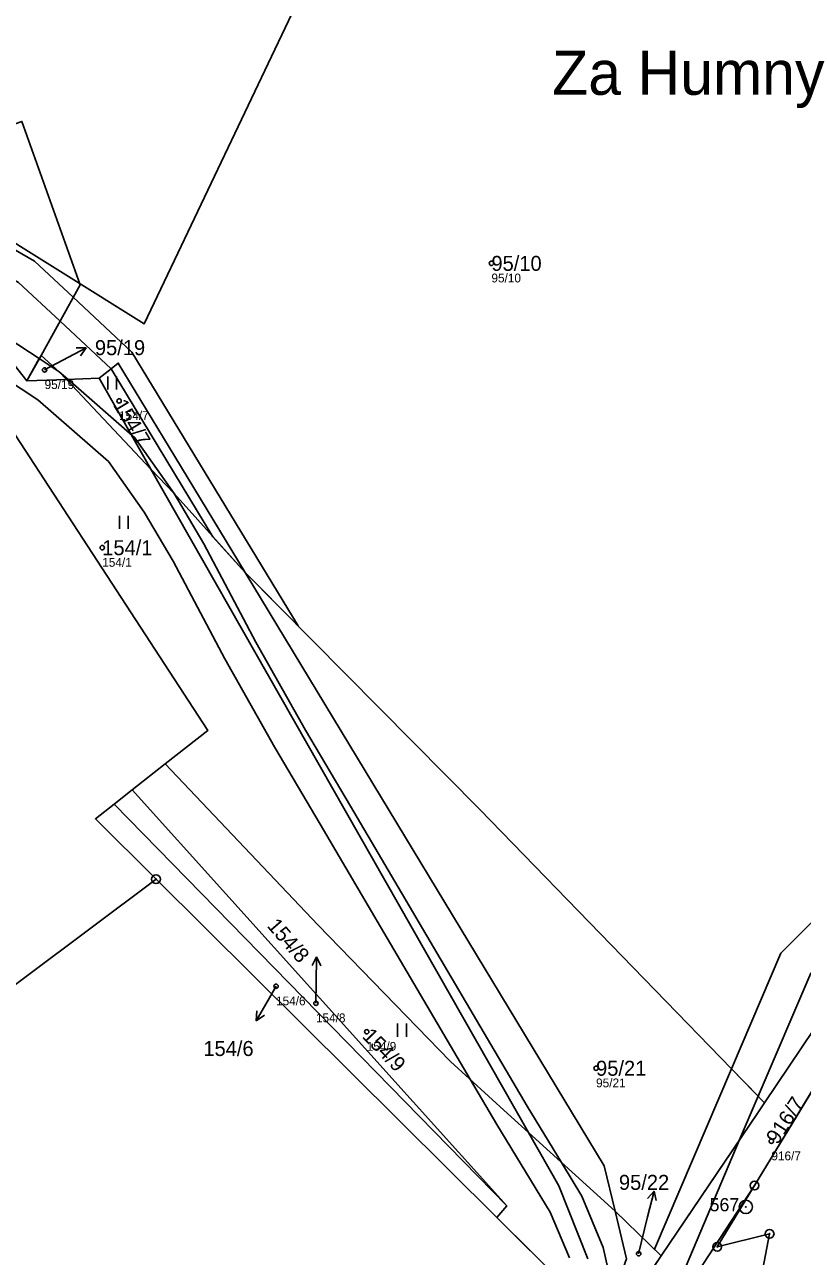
# Model space of a CAD drawing. Extents: x -734504 to -730695, y -1027923 to -1024502.
# Drawn here: x -731981.3 to -731893.3, y -1026758 to -1026618.4 of the extents above; entities that cross this region are included whole.
import ezdxf

# ---------------------------------------------------------------- set-up
doc = ezdxf.new("R2010")
doc.units = 0
for name, color, linetype in [('Definiční body', 7, 'Continuous'), ('Hranice parcel', 7, 'Continuous'), ('Parcelní čísla', 7, 'Continuous'), ('Polygon parcely', 7, 'Continuous'), ('Pop  PČ popisy', 7, 'Continuous'), ('Vnitřní kresba', 7, 'Continuous'), ('Věcná břemena k části', 7, 'Continuous'), ('Značky bodu BP', 7, 'Continuous'), ('Značky kultur', 7, 'Continuous')]:
    doc.layers.add(name, color=color, linetype=linetype)

msp = doc.modelspace()

# ---------------------------------------------------------------- linework, layer by layer
at = {"layer": 'Definiční body'}
for centre in [(-731928.49, -1026645.47), (-731979.09, -1026657.55), (-731970.65, -1026661.06), (-731972.56, -1026677.69), (-731952.88, -1026727.39), (-731948.36, -1026729.31), (-731942.61, -1026732.54), (-731916.64, -1026736.68), (-731896.79, -1026744.95), (-731911.82, -1026757.7)]:
    msp.add_circle(centre, 0.25, dxfattribs=at)
at = {"layer": 'Hranice parcel'}
for p, q in [((-731998.09, -1026637.25), (-731981.09, -1026658.8)), ((-731981.09, -1026658.8), (-731979.49, -1026655.91)), ((-731976.61, -1026658.62), (-731981.09, -1026658.8)), ((-731915.73, -1026747.72), (-731956.39, -1026680.5)), ((-731969.17, -1026705.14), (-731965.42, -1026702.19)), ((-731971.2, -1026706.74), (-731969.17, -1026705.14)), ((-731926.76, -1026752.28), (-731969.17, -1026705.14)), ((-731926.76, -1026752.28), (-731971.2, -1026706.74)), ((-731927.88, -1026753.59), (-731966.47, -1026715.25)), ((-731886.31, -1026729.58), (-731898.7, -1026749.97)), ((-731914.49, -1026752.89), (-731915.73, -1026747.72)), ((-731927.88, -1026753.59), (-731926.76, -1026752.28)), ((-731914.49, -1026752.89), (-731909.26, -1026757.93)), ((-731919.78, -1026761.63), (-731927.88, -1026753.59))]:
    msp.add_line(p, q, dxfattribs=at)
for points in [[(-731979.49, -1026655.91), (-731975.06, -1026647.92), (-731981.65, -1026629.39), (-731996.27, -1026634.52)], [(-731965.42, -1026702.19), (-731960.6, -1026698.4), (-731989.51, -1026654.05), (-731999.43, -1026638.83)], [(-731979.49, -1026655.91), (-731977.42, -1026657.76), (-731976.61, -1026658.62)], [(-731976.61, -1026658.62), (-731972.9, -1026658.47), (-731971.56, -1026657.43), (-731970.74, -1026656.78)], [(-731970.74, -1026656.78), (-731964.35, -1026667.34), (-731956.39, -1026680.5)], [(-731956.39, -1026680.5), (-731964.43, -1026671.55), (-731967.04, -1026668.78), (-731976.61, -1026658.62)], [(-731897.55, -1026740.6), (-731891.98, -1026732.29), (-731883.98, -1026721.82), (-731870.03, -1026706.66), (-731852.36, -1026688.4), (-731836.27, -1026672.06)], [(-731956.39, -1026680.5), (-731929.79, -1026707.37), (-731897.55, -1026740.6)], [(-731965.42, -1026702.19), (-731948.13, -1026720.44), (-731933.11, -1026735.93), (-731926.68, -1026741.8), (-731924.3, -1026743.96), (-731914.49, -1026752.89)], [(-731966.47, -1026715.25), (-731973.34, -1026708.42), (-731971.2, -1026706.74)], [(-732007.28, -1026745.77), (-731989.29, -1026732.31), (-731988.74, -1026731.9), (-731966.47, -1026715.25)], [(-731909.26, -1026757.93), (-731898.31, -1026741.73), (-731897.55, -1026740.6)], [(-731898.7, -1026749.97), (-731907.76, -1026763.82), (-731909.1, -1026766.06)], [(-731898.7, -1026749.97), (-731902.92, -1026756.92), (-731896.99, -1026755.44), (-731899.12, -1026766.53)], [(-731914.49, -1026752.89), (-731913.19, -1026758.29), (-731915.79, -1026765.55)], [(-731917.71, -1026772.7), (-731911.78, -1026761.66), (-731909.26, -1026757.93)]]:
    msp.add_lwpolyline(points, dxfattribs=at)
at = {"layer": 'Polygon parcely'}
for points in [[(-731863.15, -1026642.98), (-731906.94, -1026596.3), (-731941.3, -1026559.94), (-732003.69, -1026606.79), (-732006.1, -1026609.2), (-732012.91, -1026616.02), (-732013.85, -1026616.96), (-732011.19, -1026619.62), (-731996.27, -1026634.52), (-731981.65, -1026629.39), (-731975.06, -1026647.92), (-731979.49, -1026655.91), (-731977.42, -1026657.76), (-731976.61, -1026658.62), (-731972.9, -1026658.47), (-731971.56, -1026657.43), (-731970.74, -1026656.78), (-731964.35, -1026667.34), (-731956.39, -1026680.5), (-731929.79, -1026707.37), (-731897.55, -1026740.6), (-731891.98, -1026732.29)], [(-731907.76, -1026763.82), (-731898.7, -1026749.97), (-731886.31, -1026729.58), (-731884.4, -1026726.44), (-731842.6, -1026684.43), (-731833.2, -1026674.32), (-731829.04, -1026668.66), (-731807.05, -1026644.37), (-731800.24, -1026636.86), (-731792.35, -1026628.32), (-731782.06, -1026616.62), (-731778.03, -1026612.05), (-731780.21, -1026614.31), (-731805.23, -1026640.33), (-731828.58, -1026664.25), (-731836.27, -1026672.06), (-731852.36, -1026688.4), (-731870.03, -1026706.66), (-731883.98, -1026721.82), (-731891.98, -1026732.29), (-731897.55, -1026740.6), (-731898.31, -1026741.73), (-731909.26, -1026757.93), (-731911.78, -1026761.66)], [(-731988.74, -1026731.9), (-731966.47, -1026715.25), (-731973.34, -1026708.42), (-731971.2, -1026706.74), (-731969.17, -1026705.14), (-731965.42, -1026702.19), (-731960.6, -1026698.4), (-731989.51, -1026654.05)]]:
    msp.add_lwpolyline(points, dxfattribs=at)
for points in [[(-731975.06, -1026647.92), (-731981.65, -1026629.39), (-731996.27, -1026634.52), (-731996.97, -1026635.57), (-731998.09, -1026637.25), (-731981.09, -1026658.8), (-731979.49, -1026655.91)], [(-731933.11, -1026735.93), (-731926.68, -1026741.8), (-731924.3, -1026743.96), (-731914.49, -1026752.89), (-731915.73, -1026747.72), (-731956.39, -1026680.5), (-731964.43, -1026671.55), (-731967.04, -1026668.78), (-731976.61, -1026658.62), (-731981.09, -1026658.8), (-731998.09, -1026637.25), (-731998.74, -1026638.02), (-731999.43, -1026638.83), (-731989.51, -1026654.05), (-731960.6, -1026698.4), (-731965.42, -1026702.19), (-731948.13, -1026720.44)], [(-731979.49, -1026655.91), (-731981.09, -1026658.8), (-731976.61, -1026658.62), (-731977.42, -1026657.76)], [(-731970.74, -1026656.78), (-731971.56, -1026657.43), (-731972.9, -1026658.47), (-731976.61, -1026658.62), (-731967.04, -1026668.78), (-731964.43, -1026671.55), (-731956.39, -1026680.5), (-731964.35, -1026667.34)], [(-731909.26, -1026757.93), (-731898.31, -1026741.73), (-731897.55, -1026740.6), (-731929.79, -1026707.37), (-731956.39, -1026680.5), (-731915.73, -1026747.72), (-731914.49, -1026752.89)], [(-731919.78, -1026761.63), (-731915.79, -1026765.55), (-731913.19, -1026758.29), (-731914.49, -1026752.89), (-731924.3, -1026743.96), (-731926.68, -1026741.8), (-731933.11, -1026735.93), (-731948.13, -1026720.44), (-731965.42, -1026702.19), (-731969.17, -1026705.14), (-731926.76, -1026752.28), (-731927.88, -1026753.59)], [(-731926.76, -1026752.28), (-731969.17, -1026705.14), (-731971.2, -1026706.74)], [(-731926.76, -1026752.28), (-731971.2, -1026706.74), (-731973.34, -1026708.42), (-731966.47, -1026715.25), (-731927.88, -1026753.59)], [(-732041.57, -1026826.46), (-732021.92, -1026852.62), (-731966.12, -1026808.48), (-731919.78, -1026761.63), (-731927.88, -1026753.59), (-731966.47, -1026715.25), (-731988.74, -1026731.9), (-731989.29, -1026732.31), (-732007.28, -1026745.77), (-731985.19, -1026775.31), (-731997.89, -1026784.9), (-732020.01, -1026755.28), (-732024.83, -1026758.88), (-732027.73, -1026761.05), (-732068.04, -1026791.19), (-732043.87, -1026823.31)], [(-731896.99, -1026755.44), (-731899.12, -1026766.53), (-731892.84, -1026760.35), (-731891.79, -1026759.14), (-731882.22, -1026753.42), (-731867.68, -1026758.34), (-731883.36, -1026734.14), (-731886.31, -1026729.58), (-731898.7, -1026749.97), (-731902.92, -1026756.92)], [(-731908.97, -1026773), (-731907.29, -1026774.21), (-731903.36, -1026770.7), (-731899.12, -1026766.53), (-731896.99, -1026755.44), (-731902.92, -1026756.92), (-731898.7, -1026749.97), (-731907.76, -1026763.82), (-731909.1, -1026766.06), (-731910.12, -1026767.76)], [(-731913.19, -1026758.29), (-731915.79, -1026765.55), (-731917.71, -1026772.7), (-731911.78, -1026761.66), (-731909.26, -1026757.93), (-731914.49, -1026752.89)]]:
    msp.add_lwpolyline(points, close=True, dxfattribs=at)
at = {"layer": 'Pop  PČ popisy'}
for p, q in [((-731977.03, -1026656.44), (-731974.38, -1026655.03)), ((-731974.38, -1026655.03), (-731975.5, -1026655.06)), ((-731974.38, -1026655.03), (-731975.03, -1026655.94)), ((-731979.09, -1026657.55), (-731977.03, -1026656.44)), ((-731948.28, -1026724.05), (-731948.8, -1026725.04)), ((-731948.33, -1026727.05), (-731948.28, -1026724.05)), ((-731948.28, -1026724.05), (-731947.79, -1026725.06)), ((-731952.88, -1026727.39), (-731953.62, -1026728.69)), ((-731948.36, -1026729.31), (-731948.33, -1026727.05)), ((-731953.62, -1026728.69), (-731955.12, -1026731.29)), ((-731955.12, -1026731.29), (-731955.05, -1026730.17)), ((-731955.12, -1026731.29), (-731954.19, -1026730.67)), ((-731910.8, -1026753.5), (-731910.07, -1026750.59)), ((-731910.07, -1026750.59), (-731910.8, -1026751.44)), ((-731910.07, -1026750.59), (-731909.83, -1026751.68)), ((-731911.82, -1026757.7), (-731910.8, -1026753.5))]:
    msp.add_line(p, q, dxfattribs=at)
at = {"layer": 'Vnitřní kresba'}
for p, q in [((-731972.9, -1026658.47), (-731967.04, -1026668.78)), ((-731967.04, -1026668.78), (-731924.3, -1026743.96)), ((-731924.3, -1026743.96), (-731920.86, -1026750.02)), ((-731917.58, -1026758.29), (-731920.86, -1026750.02))]:
    msp.add_line(p, q, dxfattribs=at)
msp.add_lwpolyline([(-732061.13, -1026537.35), (-732085.01, -1026542.48), (-732078.92, -1026559.32), (-732073.63, -1026577.76), (-732071.73, -1026591.42), (-732069.62, -1026609.74), (-732068.98, -1026636.13), (-732059.46, -1026625.23), (-732039.49, -1026615.52), (-732026.13, -1026613.13), (-732013.67, -1026616.52), (-731996.27, -1026634.52), (-731967.83, -1026652.33), (-731949.59, -1026613.99), (-731927.58, -1026565.74), (-731904.67, -1026526.33)], dxfattribs=at)
at = {"layer": 'Věcná břemena k části'}
for points in [[(-731980.24, -1026645.21), (-731996.97, -1026635.57), (-732001.13, -1026633.18), (-732001.93, -1026633.03), (-731999.49, -1026635.71), (-731998.09, -1026637.25), (-731996.43, -1026639.35), (-731982.04, -1026647.63), (-731977.34, -1026652.03), (-731971.56, -1026657.43), (-731960.03, -1026676.45), (-731956.39, -1026680.5), (-731950.39, -1026686.56), (-731969.2, -1026655.53), (-731975.84, -1026649.32)], [(-731987.78, -1026650.32), (-731981.09, -1026658.8), (-731979.69, -1026656.27), (-731983.11, -1026654.03)], [(-731976.44, -1026658.61), (-731977.42, -1026657.76), (-731976.61, -1026658.62), (-731967.04, -1026668.78), (-731964.43, -1026671.55), (-731968.86, -1026665.24)], [(-731840.03, -1026673.33), (-731837.58, -1026670.8), (-731840.47, -1026668.03), (-731842.89, -1026670.53), (-731895.7, -1026723.64), (-731901.3, -1026736.73), (-731898.28, -1026739.85), (-731892.32, -1026725.92)], [(-731901.3, -1026736.73), (-731910.04, -1026757.17), (-731909.26, -1026757.93), (-731900.42, -1026744.86), (-731898.28, -1026739.85)], [(-732024.55, -1026865.8), (-732022.11, -1026868.92), (-732016.59, -1026864.76), (-732016.09, -1026864.38), (-732015.49, -1026865.31), (-732012.33, -1026862.83), (-732012.87, -1026862), (-732004.32, -1026854.61), (-732002.58, -1026852.67), (-731988.8, -1026840.23), (-731972.85, -1026825.75), (-731946.21, -1026802.13), (-731933.94, -1026790.88), (-731909.79, -1026766.75), (-731907.68, -1026762.03), (-731900.42, -1026744.86), (-731909.26, -1026757.93), (-731911.19, -1026760.79), (-731911.78, -1026761.66), (-731912.67, -1026763.32), (-731917.3, -1026774.14), (-732015.07, -1026858.63), (-732018.93, -1026861.55)]]:
    msp.add_lwpolyline(points, close=True, dxfattribs=at)
for points in [[(-731915.32, -1026759.34), (-731915.82, -1026756.99), (-731918.26, -1026751.17), (-731920.57, -1026747.35), (-731924.43, -1026740.99), (-731936.68, -1026720.21), (-731944.43, -1026706.97), (-731949.56, -1026698.35), (-731955.16, -1026688.38), (-731961.05, -1026677.24), (-731964.43, -1026671.55), (-731967.04, -1026668.78), (-731976.61, -1026658.62), (-731977.42, -1026657.76), (-731979.69, -1026656.27), (-731981.09, -1026658.8), (-731987.78, -1026650.32)], [(-731985.45, -1026657.27), (-731979.85, -1026660.95), (-731971.85, -1026667.94), (-731967.83, -1026673.67), (-731964.54, -1026679.2), (-731958.68, -1026690.29), (-731953.02, -1026700.35), (-731947.88, -1026709.01), (-731940.3, -1026721.95), (-731930.85, -1026737.99), (-731927.87, -1026743.05), (-731921.84, -1026752.99), (-731919.66, -1026758.18)]]:
    msp.add_lwpolyline(points, dxfattribs=at)
at = {"layer": 'Značky bodu BP'}
for centre, radius in [((-731966.47, -1026715.25), 0.5), ((-731966.47, -1026715.25), 0.0303), ((-731898.7, -1026749.97), 0.5), ((-731898.7, -1026749.97), 0.0303), ((-731899.68, -1026752.39), 0.75), ((-731899.68, -1026752.39), 0.03), ((-731896.99, -1026755.44), 0.5), ((-731896.99, -1026755.44), 0.0303), ((-731902.92, -1026756.92), 0.5), ((-731902.92, -1026756.92), 0.0303)]:
    msp.add_circle(centre, radius, dxfattribs=at)
at = {"layer": 'Značky kultur'}
for p, q in [((-731971.94, -1026659.78), (-731971.94, -1026658.28)), ((-731970.94, -1026659.78), (-731970.94, -1026658.28)), ((-731970.62, -1026675.57), (-731970.62, -1026674.07)), ((-731969.62, -1026675.57), (-731969.62, -1026674.07)), ((-731939.12, -1026733.12), (-731939.12, -1026731.62)), ((-731938.12, -1026733.12), (-731938.12, -1026731.62))]:
    msp.add_line(p, q, dxfattribs=at)

# ---------------------------------------------------------------- texts
at = {"layer": 'Definiční body'}
for s, p in [('95/10', (-731928.49, -1026647.63)), ('95/19', (-731979.09, -1026659.71)), ('154/7', (-731970.65, -1026663.22)), ('154/1', (-731972.56, -1026679.85)), ('154/6', (-731952.88, -1026729.55)), ('154/8', (-731948.36, -1026731.47)), ('154/9', (-731942.61, -1026734.7)), ('95/21', (-731916.64, -1026738.84)), ('916/7', (-731896.79, -1026747.11))]:
    msp.add_text(s, height=1, dxfattribs=at).set_placement(p)
at = {"layer": 'Parcelní čísla'}
for s, p in [('95/10', (-731928.49, -1026646.32)), ('95/19', (-731973.39, -1026655.87)), ('154/1', (-731972.56, -1026678.54)), ('154/6', (-731961.11, -1026735.29)), ('95/21', (-731916.64, -1026737.53)), ('95/22', (-731914.05, -1026750.46))]:
    msp.add_text(s, height=1.7, dxfattribs=at).set_placement(p)
for s, rotation, p in [('154/7', 301, (-731971.38, -1026661.5)), ('154/8', 311, (-731953.98, -1026720.59)), ('154/9', 314, (-731943.22, -1026733.13)), ('916/7', 57, (-731896.08, -1026745.41))]:
    msp.add_text(s, height=1.7, rotation=rotation, dxfattribs=at).set_placement(p)
at = {"layer": 'Pop  PČ popisy'}
msp.add_text('Za Humny', height=5, dxfattribs=at).set_placement((-731921.61, -1026626.37))
at = {"layer": 'Značky bodu BP'}
msp.add_text('567', height=1.5, dxfattribs=at).set_placement((-731903.78, -1026752.89))

doc.saveas('drawing.dxf')
